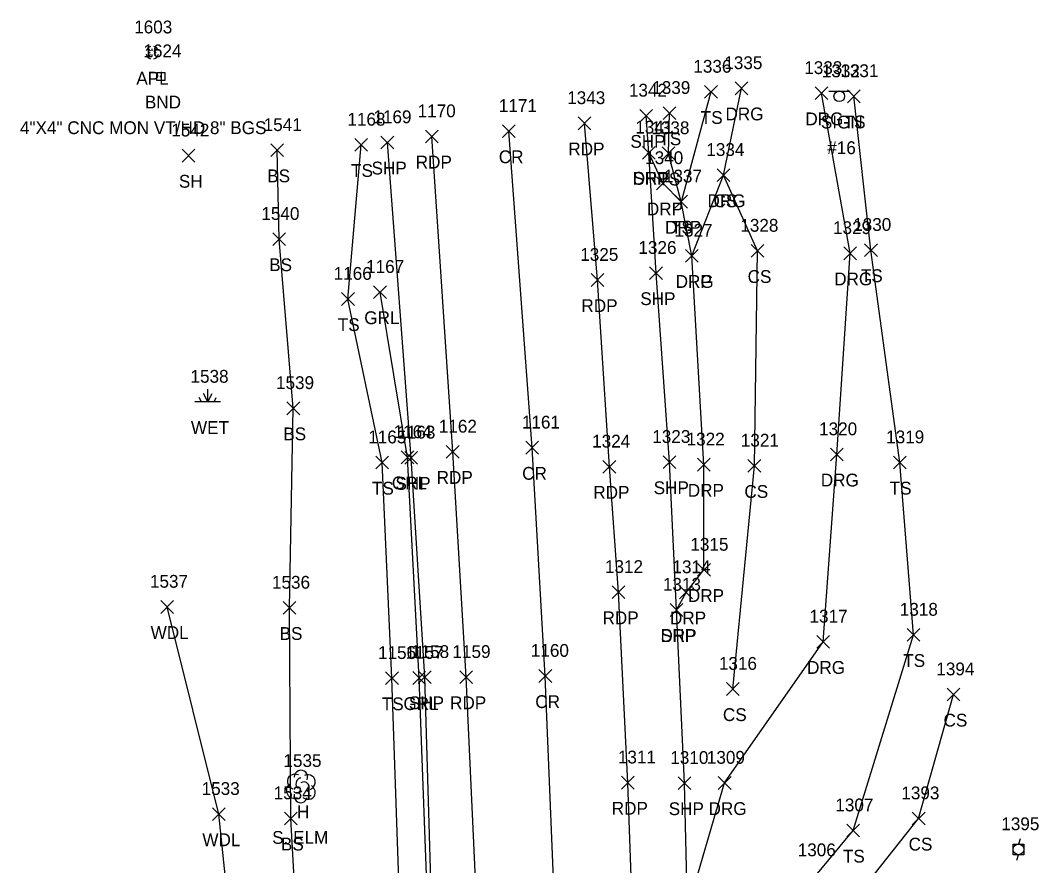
# Model space of a CAD drawing. Extents: x 1618262 to 1622220, y 273782 to 283685.
# Drawn here: x 1621978.9 to 1622138, y 282818.4 to 282950.4 of the extents above; entities that cross this region are included whole.
import ezdxf

# ---------------------------------------------------------------- set-up
doc = ezdxf.new("R2010")
doc.units = 0
for name, color, linetype in [('L_A', 7, 'Continuous'), ('L_C', 7, 'Continuous'), ('L_I', 7, 'Continuous'), ('L_TIC', 7, 'Continuous'), ('LAWA', 7, 'Continuous'), ('LELB', 7, 'Continuous'), ('LTD', 7, 'Continuous'), ('LWET', 7, 'Continuous'), ('M_A', 7, 'Continuous'), ('M_C', 7, 'Continuous'), ('M_I', 7, 'Continuous'), ('MHBP', 7, 'Continuous'), ('MMP', 7, 'Continuous'), ('P_A', 7, 'Continuous'), ('P_I', 7, 'Continuous'), ('P_TIC', 7, 'Continuous'), ('PET', 7, 'Continuous'), ('PRC', 7, 'Continuous'), ('PSP', 7, 'Continuous'), ('R_A', 7, 'Continuous'), ('R_I', 7, 'Continuous'), ('R_TIC', 7, 'Continuous'), ('RDG', 7, 'Continuous'), ('RDP', 7, 'Continuous'), ('RGR', 7, 'Continuous'), ('S_A', 7, 'Continuous'), ('S_C', 7, 'Continuous'), ('S_I', 7, 'Continuous'), ('SSGN', 7, 'Continuous'), ('U_I', 7, 'Continuous'), ('UP', 7, 'Continuous')]:
    doc.layers.add(name, color=color, linetype=linetype)

msp = doc.modelspace()

# ---------------------------------------------------------------- linework, layer by layer
at = {"layer": 'L_TIC'}
for points in [[(1622085.84, 282938.24), (1622087.84, 282940.24)], [(1622087.84, 282938.24), (1622085.84, 282940.24)], [(1622108.18, 282937.55), (1622110.18, 282939.55)], [(1622110.18, 282937.55), (1622108.18, 282939.55)], [(1622079.37, 282934.92), (1622081.37, 282936.92)], [(1622081.37, 282934.92), (1622079.37, 282936.92)], [(1622031.2, 282929.97), (1622033.2, 282931.97)], [(1622033.2, 282929.97), (1622031.2, 282931.97)], [(1622004.21, 282928.28), (1622006.21, 282930.28)], [(1622006.21, 282928.28), (1622004.21, 282930.28)], [(1622018.07, 282929.13), (1622020.07, 282931.13)], [(1622020.07, 282929.13), (1622018.07, 282931.13)], [(1622079.22, 282928.64), (1622081.22, 282930.64)], [(1622081.22, 282928.64), (1622079.22, 282930.64)], [(1622087.81, 282925.24), (1622089.81, 282927.24)], [(1622089.81, 282925.24), (1622087.81, 282927.24)], [(1622081.18, 282921.1), (1622083.18, 282923.1)], [(1622083.18, 282921.1), (1622081.18, 282923.1)], [(1622018.37, 282915.25), (1622020.37, 282917.25)], [(1622020.37, 282915.25), (1622018.37, 282917.25)], [(1622093.12, 282913.41), (1622095.12, 282915.41)], [(1622095.12, 282913.41), (1622093.12, 282915.41)], [(1622110.85, 282913.54), (1622112.85, 282915.54)], [(1622112.85, 282913.54), (1622110.85, 282915.54)], [(1622029.12, 282905.9), (1622031.12, 282907.9)], [(1622031.12, 282905.9), (1622029.12, 282907.9)], [(1622020.58, 282888.84), (1622022.58, 282890.84)], [(1622022.58, 282888.84), (1622020.58, 282890.84)], [(1622034.47, 282880.36), (1622036.47, 282882.36)], [(1622036.47, 282880.36), (1622034.47, 282882.36)], [(1622115.35, 282880.37), (1622117.35, 282882.37)], [(1622117.35, 282880.37), (1622115.35, 282882.37)], [(1622092.63, 282879.85), (1622094.63, 282881.85)], [(1622094.63, 282879.85), (1622092.63, 282881.85)], [(1622000.87, 282857.82), (1622002.87, 282859.82)], [(1622002.87, 282857.82), (1622000.87, 282859.82)], [(1622020, 282857.67), (1622022, 282859.67)], [(1622022, 282857.67), (1622020, 282859.67)], [(1622117.48, 282853.45), (1622119.48, 282855.45)], [(1622119.48, 282853.45), (1622117.48, 282855.45)], [(1622036, 282846.69), (1622038, 282848.69)], [(1622038, 282846.69), (1622036, 282848.69)], [(1622089.27, 282845), (1622091.27, 282847)], [(1622091.27, 282845), (1622089.27, 282847)], [(1622123.75, 282844.14), (1622125.75, 282846.14)], [(1622125.75, 282844.14), (1622123.75, 282846.14)], [(1622008.95, 282825.46), (1622010.95, 282827.46)], [(1622010.95, 282825.46), (1622008.95, 282827.46)], [(1622020.21, 282824.79), (1622022.21, 282826.79)], [(1622022.21, 282824.79), (1622020.21, 282826.79)], [(1622118.29, 282824.78), (1622120.29, 282826.78)], [(1622120.29, 282824.78), (1622118.29, 282826.78)], [(1622108.05, 282822.9), (1622110.05, 282824.9)], [(1622110.05, 282822.9), (1622108.05, 282824.9)]]:
    msp.add_lwpolyline(points, dxfattribs=at)
at = {"layer": 'LAWA'}
msp.add_lwpolyline([(1622012.26, 282719.26), (1622015.51, 282741.12), (1622016.4, 282766.92), (1622013, 282796.99), (1622009.95, 282826.46), (1622001.87, 282858.82)], dxfattribs=at)
at = {"layer": 'LELB'}
for points in [[(1622086.84, 282939.24), (1622082.18, 282922.1), (1622080.22, 282929.64), (1622080.37, 282935.92)], [(1622121.16, 282596.52), (1622112.16, 282596.84), (1622102.98, 282598.76), (1622094.2, 282601.85), (1622088.69, 282605.57), (1622085.73, 282618.96), (1622084.9, 282649.7), (1622087.6, 282681.1), (1622086.98, 282710.97), (1622088.16, 282744.85), (1622088.43, 282782.06), (1622089.47, 282801.31), (1622094.58, 282809.14), (1622103.23, 282816.89), (1622109.05, 282823.9), (1622118.48, 282854.45), (1622116.35, 282881.37), (1622111.85, 282914.54), (1622109.18, 282938.55)], [(1622011.79, 282703.52), (1622017.8, 282718.9), (1622019.25, 282742.06), (1622019.35, 282767.74), (1622022.85, 282795.88), (1622021.21, 282825.79), (1622021, 282858.67), (1622021.58, 282889.84), (1622019.37, 282916.25), (1622019.07, 282930.13)], [(1622031.53, 282480.21), (1622034.92, 282519.52), (1622036.31, 282559.67), (1622038.55, 282600.48), (1622040.58, 282634.79), (1622041.38, 282671.63), (1622041.06, 282708.26), (1622040.54, 282746.86), (1622039.33, 282766.47), (1622038.37, 282807.15), (1622037, 282847.69), (1622035.47, 282881.36), (1622030.12, 282906.9), (1622032.2, 282930.97)], [(1622090.27, 282846), (1622093.63, 282880.85), (1622094.12, 282914.41), (1622088.81, 282926.24)], [(1622091.19, 282690.57), (1622090.7, 282707.3), (1622092.69, 282721.62), (1622095.2, 282734.09), (1622093.37, 282753.63), (1622092.46, 282776.61), (1622095.59, 282800.79), (1622106.62, 282809.83), (1622119.29, 282825.78), (1622124.75, 282845.14)]]:
    msp.add_lwpolyline(points, dxfattribs=at)
at = {"layer": 'LTD'}
msp.add_line((1622022.74, 282830.83), (1622022.74, 282830.83), dxfattribs=at)
msp.add_line((1622022.74, 282830.83), (1622022.74, 282830.83), dxfattribs=at)
msp.add_arc((1622022.78, 282832.27), 1.05, 335.5272, 180.9563, dxfattribs=at)
for centre, major_axis, ratio, start_param, end_param in [((1622021.94, 282831.5), (1.21, -0.51), 0.895232, 1.570796, 4.712389), ((1622022.53, 282831.29), (-0.208, -0.792), 0.645439, 3.141593, 6.283185), ((1622023.24, 282830.67), (-0.5, 0.667), 0.989748, 3.141593, 6.283185), ((1622023.78, 282831.42), (-1.14, -0.48), 0.949671, 1.570796, 4.712389), ((1622021.65, 282830.12), (0.58, -1.04), 0.959034, 3.141593, 6.283185), ((1622022.28, 282830.08), (-0.625, -0.083), 0.423636, 0, 3.141593), ((1622023.74, 282830), (-1.09, 0.79), 0.841452, 1.570796, 4.712389), ((1622022.74, 282829.33), (0.26, 1.06), 0.942809, 1.570796, 4.712389)]:
    msp.add_ellipse(centre, major_axis=major_axis, ratio=ratio, start_param=start_param, end_param=end_param, dxfattribs=at)
at = {"layer": 'LWET'}
for p, q in [((1622008.22, 282890.83), (1622007.55, 282892.16)), ((1622008.22, 282890.83), (1622008.22, 282892.83)), ((1622008.22, 282890.83), (1622008.88, 282892.16)), ((1622010.22, 282890.83), (1622006.22, 282890.83)), ((1622007.22, 282890.83), (1622006.88, 282891.5)), ((1622009.22, 282890.83), (1622009.55, 282891.5))]:
    msp.add_line(p, q, dxfattribs=at)
at = {"layer": 'MHBP'}
msp.add_lwpolyline([(1622000.28, 282942.27), (1622001.53, 282942.27), (1622001.53, 282941.02), (1622000.28, 282941.02)], close=True, dxfattribs=at)
msp.add_circle((1622000.9, 282941.65), 0.0833, dxfattribs=at)
at = {"layer": 'MMP'}
for p, q in [((1621998.9, 282946.02), (1621999.26, 282945.66)), ((1621999.54, 282945.68), (1621999.54, 282945.98)), ((1621999.82, 282945.66), (1622000.18, 282946.02)), ((1621998.9, 282944.74), (1621999.26, 282945.1)), ((1621998.94, 282945.38), (1621999.24, 282945.38)), ((1621999.54, 282944.78), (1621999.54, 282945.08)), ((1621999.82, 282945.1), (1622000.18, 282944.74)), ((1621999.84, 282945.38), (1622000.14, 282945.38))]:
    msp.add_line(p, q, dxfattribs=at)
for start, end in [(105, 165), (15, 75), (195, 255), (285, 345)]:
    msp.add_arc((1621999.54, 282945.38), 1, start, end, dxfattribs=at)
at = {"layer": 'P_TIC'}
for points in [[(1622075.71, 282934.51), (1622077.71, 282936.51)], [(1622077.71, 282934.51), (1622075.71, 282936.51)], [(1622066.07, 282933.34), (1622068.07, 282935.34)], [(1622068.07, 282933.34), (1622066.07, 282935.34)], [(1622042.22, 282931.28), (1622044.22, 282933.28)], [(1622044.22, 282931.28), (1622042.22, 282933.28)], [(1622054.26, 282932.11), (1622056.26, 282934.11)], [(1622056.26, 282932.11), (1622054.26, 282934.11)], [(1622035.28, 282930.35), (1622037.28, 282932.35)], [(1622037.28, 282930.35), (1622035.28, 282932.35)], [(1622076.13, 282928.74), (1622078.13, 282930.74)], [(1622078.13, 282928.74), (1622076.13, 282930.74)], [(1622068.11, 282908.86), (1622070.11, 282910.86)], [(1622070.11, 282908.86), (1622068.11, 282910.86)], [(1622077.26, 282909.95), (1622079.26, 282911.95)], [(1622079.26, 282909.95), (1622077.26, 282911.95)], [(1622045.49, 282882.04), (1622047.49, 282884.04)], [(1622047.49, 282882.04), (1622045.49, 282884.04)], [(1622057.91, 282882.68), (1622059.91, 282884.68)], [(1622059.91, 282882.68), (1622057.91, 282884.68)], [(1622039.01, 282881.11), (1622041.01, 282883.11)], [(1622041.01, 282881.11), (1622039.01, 282883.11)], [(1622079.36, 282880.43), (1622081.36, 282882.43)], [(1622081.36, 282880.43), (1622079.36, 282882.43)], [(1622069.97, 282879.71), (1622071.97, 282881.71)], [(1622071.97, 282879.71), (1622069.97, 282881.71)], [(1622071.41, 282860.12), (1622073.41, 282862.12)], [(1622073.41, 282860.12), (1622071.41, 282862.12)], [(1622080.46, 282857.35), (1622082.46, 282859.35)], [(1622082.46, 282857.35), (1622080.46, 282859.35)], [(1622041.11, 282846.85), (1622043.11, 282848.85)], [(1622043.11, 282846.85), (1622041.11, 282848.85)], [(1622047.59, 282846.85), (1622049.59, 282848.85)], [(1622049.59, 282846.85), (1622047.59, 282848.85)], [(1622059.96, 282847.03), (1622061.96, 282849.03)], [(1622061.96, 282847.03), (1622059.96, 282849.03)], [(1622072.85, 282830.38), (1622074.85, 282832.38)], [(1622074.85, 282830.38), (1622072.85, 282832.38)], [(1622081.7, 282830.31), (1622083.7, 282832.31)], [(1622083.7, 282830.31), (1622081.7, 282832.31)]]:
    msp.add_lwpolyline(points, dxfattribs=at)
at = {"layer": 'PET'}
for points in [[(1622055.39, 282357.79), (1622060.73, 282405.55), (1622064, 282439.1), (1622067.39, 282476.75), (1622069.45, 282501.97), (1622071.17, 282531.22), (1622072.59, 282558.99), (1622074.38, 282609.31), (1622075.4, 282650.49), (1622076.38, 282682.88), (1622076.73, 282709.49), (1622076.47, 282742.79), (1622075.65, 282781.75), (1622073.85, 282831.38), (1622072.41, 282861.12), (1622070.97, 282880.71), (1622069.11, 282909.86), (1622067.07, 282934.34)], [(1622031.4, 282363.08), (1622036.53, 282409.61), (1622039.66, 282443.45), (1622042.91, 282478.81), (1622045.92, 282518.25), (1622048.16, 282558.34), (1622049.91, 282599.51), (1622051.11, 282634.14), (1622051.9, 282670.59), (1622052.33, 282709.81), (1622052.15, 282746.85), (1622051.43, 282768.15), (1622050.47, 282807.31), (1622048.59, 282847.85), (1622046.49, 282883.04), (1622043.22, 282932.28)]]:
    msp.add_lwpolyline(points, dxfattribs=at)
at = {"layer": 'PRC'}
msp.add_lwpolyline([(1622043.29, 282360.39), (1622048.9, 282407.64), (1622051.69, 282440.97), (1622055.31, 282477.63), (1622057.87, 282516.74), (1622059.99, 282557.51), (1622061.58, 282597.2), (1622062.84, 282633.2), (1622063.88, 282668.54), (1622064.41, 282708.38), (1622064.5, 282747.03), (1622063.87, 282768.18), (1622062.59, 282807.54), (1622060.96, 282848.03), (1622058.91, 282883.68), (1622055.26, 282933.11)], dxfattribs=at)
at = {"layer": 'PSP'}
for points in [[(1622063.9, 282356.42), (1622068.96, 282404.45), (1622072.02, 282437.73), (1622074.67, 282475.61), (1622076.63, 282501.43), (1622078.27, 282531.06), (1622079.38, 282546.3), (1622079.58, 282558.79), (1622081.73, 282610.73), (1622082.59, 282649.97), (1622083.39, 282682.72), (1622083.74, 282709.96), (1622083.62, 282744.12), (1622083.45, 282781.35), (1622083.17, 282811.55), (1622082.7, 282831.31), (1622081.46, 282858.35), (1622080.36, 282881.43), (1622078.26, 282910.95), (1622077.13, 282929.74), (1622076.71, 282935.51)], [(1622024.53, 282364.7), (1622029.22, 282410.34), (1622032.13, 282444.4), (1622034.72, 282480.17), (1622038.06, 282518.94), (1622040.19, 282559.98), (1622041.78, 282599.8), (1622043.58, 282635.08), (1622043.93, 282671.71), (1622044.18, 282709.62), (1622044.43, 282746.88), (1622044.14, 282766.85), (1622043.31, 282807.36), (1622042.11, 282847.85), (1622040.01, 282882.11), (1622036.28, 282931.35)]]:
    msp.add_lwpolyline(points, dxfattribs=at)
at = {"layer": 'R_TIC'}
for points in [[(1622090.62, 282938.8), (1622092.62, 282940.8)], [(1622092.62, 282938.8), (1622090.62, 282940.8)], [(1622103.11, 282938.03), (1622105.11, 282940.03)], [(1622105.11, 282938.03), (1622103.11, 282940.03)], [(1622076.13, 282928.74), (1622078.13, 282930.74)], [(1622078.13, 282928.74), (1622076.13, 282930.74)], [(1622087.81, 282925.24), (1622089.81, 282927.24)], [(1622089.81, 282925.24), (1622087.81, 282927.24)], [(1622078.34, 282923.97), (1622080.34, 282925.97)], [(1622080.34, 282923.97), (1622078.34, 282925.97)], [(1622081.18, 282921.1), (1622083.18, 282923.1)], [(1622083.18, 282921.1), (1622081.18, 282923.1)], [(1622082.84, 282912.64), (1622084.84, 282914.64)], [(1622084.84, 282912.64), (1622082.84, 282914.64)], [(1622082.84, 282912.64), (1622084.84, 282914.64)], [(1622084.84, 282912.64), (1622082.84, 282914.64)], [(1622107.61, 282913.04), (1622109.61, 282915.04)], [(1622109.61, 282913.04), (1622107.61, 282915.04)], [(1622034.13, 282906.98), (1622036.13, 282908.98)], [(1622036.13, 282906.98), (1622034.13, 282908.98)], [(1622038.44, 282881.18), (1622040.44, 282883.18)], [(1622040.44, 282881.18), (1622038.44, 282883.18)], [(1622105.52, 282881.63), (1622107.52, 282883.63)], [(1622107.52, 282881.63), (1622105.52, 282883.63)], [(1622084.73, 282880.03), (1622086.73, 282882.03)], [(1622086.73, 282880.03), (1622084.73, 282882.03)], [(1622084.75, 282863.6), (1622086.75, 282865.6)], [(1622086.75, 282863.6), (1622084.75, 282865.6)], [(1622081.95, 282860.09), (1622083.95, 282862.09)], [(1622083.95, 282860.09), (1622081.95, 282862.09)], [(1622080.46, 282857.35), (1622082.46, 282859.35)], [(1622082.46, 282857.35), (1622080.46, 282859.35)], [(1622103.37, 282852.37), (1622105.37, 282854.37)], [(1622105.37, 282852.37), (1622103.37, 282854.37)], [(1622040.25, 282846.72), (1622042.25, 282848.72)], [(1622042.25, 282846.72), (1622040.25, 282848.72)], [(1622087.98, 282830.33), (1622089.98, 282832.33)], [(1622089.98, 282830.33), (1622087.98, 282832.33)]]:
    msp.add_lwpolyline(points, dxfattribs=at)
at = {"layer": 'RDG'}
for points in [[(1622083.84, 282913.64), (1622088.81, 282926.24), (1622091.62, 282939.8)], [(1622083.17, 282811.55), (1622088.98, 282831.33), (1622104.37, 282853.37), (1622106.52, 282882.63), (1622108.61, 282914.04), (1622104.11, 282939.03)]]:
    msp.add_lwpolyline(points, dxfattribs=at)
at = {"layer": 'RDP'}
msp.add_lwpolyline([(1622081.46, 282858.35), (1622082.95, 282861.09), (1622085.75, 282864.6), (1622085.73, 282881.03), (1622083.84, 282913.64), (1622082.18, 282922.1), (1622079.34, 282924.97), (1622077.13, 282929.74)], dxfattribs=at)
at = {"layer": 'RGR'}
msp.add_lwpolyline([(1622023.48, 282364.89), (1622028.19, 282410.18), (1622031.23, 282444.19), (1622033.74, 282480.24), (1622036.8, 282518.9), (1622039.04, 282560.07), (1622040.98, 282599.77), (1622042.92, 282635.17), (1622043.06, 282671.76), (1622043.62, 282709.36), (1622043.68, 282746.97), (1622043.35, 282766.73), (1622042.76, 282807.19), (1622041.25, 282847.72), (1622039.44, 282882.18), (1622035.13, 282907.98)], dxfattribs=at)
at = {"layer": 'SSGN'}
for p, q in [((1622105.24, 282939.38), (1622108.57, 282939.38)), ((1622106.89, 282938.55), (1622106.89, 282938.55))]:
    msp.add_line(p, q, dxfattribs=at)
msp.add_circle((1622106.89, 282938.55), 0.833, dxfattribs=at)
at = {"layer": 'UP'}
for p, q in [((1622134.07, 282820.12), (1622134.07, 282821.79)), ((1622134.07, 282821.79), (1622135.73, 282821.79)), ((1622135.15, 282822.62), (1622134.9, 282821.79)), ((1622135.73, 282821.79), (1622135.73, 282820.12)), ((1622135.73, 282820.12), (1622134.07, 282820.12)), ((1622134.65, 282819.29), (1622134.9, 282820.12)), ((1622134.9, 282820.96), (1622134.9, 282820.96))]:
    msp.add_line(p, q, dxfattribs=at)
msp.add_circle((1622134.9, 282820.96), 0.833, dxfattribs=at)

# ---------------------------------------------------------------- texts
at = {"layer": 'L_A'}
for s, p in [('TS', (1622085.25, 282934.24)), ('TS', (1622107.59, 282933.55)), ('TS', (1622078.78, 282930.92)), ('BS', (1622017.51, 282925.13)), ('TS', (1622030.61, 282925.97)), ('SH', (1622003.7, 282924.28)), ('TS', (1622078.63, 282924.64)), ('CS', (1622087.25, 282921.24)), ('TS', (1622080.59, 282917.1)), ('BS', (1622017.81, 282911.25)), ('CS', (1622092.57, 282909.41)), ('TS', (1622110.26, 282909.54)), ('TS', (1622028.53, 282901.9)), ('WET', (1622005.59, 282885.83)), ('BS', (1622020.02, 282884.84)), ('TS', (1622033.87, 282876.36)), ('CS', (1622092.07, 282875.85)), ('TS', (1622114.76, 282876.37)), ('WDL', (1621999.29, 282853.82)), ('BS', (1622019.44, 282853.67)), ('TS', (1622116.89, 282849.45)), ('TS', (1622035.41, 282842.69)), ('CS', (1622088.71, 282841)), ('CS', (1622123.19, 282840.14)), ('H', (1622022.17, 282825.83)), ('WDL', (1622007.37, 282821.46)), ('BS', (1622019.65, 282820.79)), ('CS', (1622117.73, 282820.78)), ('TS', (1622107.46, 282818.9))]:
    msp.add_text(s, height=2, dxfattribs=at).set_placement(p)
at = {"layer": 'L_C'}
msp.add_text('S. ELM', height=2, dxfattribs=at).set_placement((1622018.28, 282821.83))
at = {"layer": 'L_I'}
for s, p in [('1336', (1622084.09, 282942.24)), ('1331', (1622107.06, 282941.55)), ('1339', (1622077.67, 282938.92)), ('1541', (1622016.95, 282933.13)), ('1168', (1622030.03, 282933.97)), ('1542', (1622002.52, 282932.28)), ('1338', (1622077.53, 282932.64)), ('1334', (1622086.12, 282929.24)), ('1337', (1622079.49, 282925.1)), ('1540', (1622016.59, 282919.25)), ('1328', (1622091.43, 282917.41)), ('1330', (1622109.07, 282917.54)), ('1166', (1622027.89, 282909.9)), ('1538', (1622005.52, 282893.83)), ('1539', (1622018.88, 282892.84)), ('1165', (1622033.29, 282884.36)), ('1321', (1622091.51, 282883.85)), ('1319', (1622114.22, 282884.37)), ('1537', (1621999.18, 282861.82)), ('1536', (1622018.25, 282861.67)), ('1318', (1622116.35, 282857.45)), ('1156', (1622034.82, 282850.69)), ('1316', (1622088.08, 282849)), ('1394', (1622122.06, 282848.14)), ('1535', (1622020.04, 282833.83)), ('1533', (1622007.26, 282829.46)), ('1534', (1622018.51, 282828.79)), ('1393', (1622116.59, 282828.78)), ('1307', (1622106.28, 282826.9)), ('1306', (1622100.4, 282819.89))]:
    msp.add_text(s, height=2, dxfattribs=at).set_placement(p)
at = {"layer": 'M_A'}
for s, p in [('APL', (1621997.05, 282940.38)), ('BND', (1621998.39, 282936.65))]:
    msp.add_text(s, height=2, dxfattribs=at).set_placement(p)
at = {"layer": 'M_C'}
msp.add_text('4"X4" CNC MON VT/HD 8" BGS', height=2, dxfattribs=at).set_placement((1621978.87, 282932.65))
at = {"layer": 'M_I'}
for s, p in [('1603', (1621996.72, 282948.38)), ('1624', (1621998.16, 282944.65))]:
    msp.add_text(s, height=2, dxfattribs=at).set_placement(p)
at = {"layer": 'P_A'}
for s, p in [('SHP', (1622074.25, 282930.51)), ('CR', (1622053.69, 282928.11)), ('RDP', (1622064.56, 282929.34)), ('SHP', (1622033.81, 282926.35)), ('RDP', (1622040.71, 282927.28)), ('SHP', (1622074.67, 282924.74)), ('SHP', (1622075.8, 282905.95)), ('RDP', (1622066.6, 282904.86)), ('CR', (1622057.34, 282878.68)), ('SHP', (1622037.54, 282877.11)), ('RDP', (1622043.98, 282878.04)), ('RDP', (1622068.46, 282875.71)), ('SHP', (1622077.89, 282876.43)), ('RDP', (1622069.9, 282856.12)), ('SHP', (1622079, 282853.35)), ('SHP', (1622039.64, 282842.85)), ('RDP', (1622046.08, 282842.85)), ('CR', (1622059.39, 282843.03)), ('RDP', (1622071.34, 282826.38)), ('SHP', (1622080.24, 282826.31))]:
    msp.add_text(s, height=2, dxfattribs=at).set_placement(p)
at = {"layer": 'P_I'}
for s, p in [('1342', (1622074.02, 282938.51)), ('1171', (1622053.7, 282936.11)), ('1343', (1622064.38, 282937.34)), ('1169', (1622034.1, 282934.35)), ('1170', (1622041.01, 282935.28)), ('1341', (1622075.01, 282932.74)), ('1326', (1622075.51, 282913.95)), ('1325', (1622066.42, 282912.86)), ('1161', (1622057.3, 282886.68)), ('1163', (1622037.83, 282885.11)), ('1162', (1622044.32, 282886.04)), ('1324', (1622068.28, 282883.71)), ('1323', (1622077.67, 282884.43)), ('1312', (1622070.28, 282864.12)), ('1313', (1622079.33, 282861.35)), ('1158', (1622039.98, 282850.85)), ('1159', (1622046.45, 282850.85)), ('1160', (1622058.7, 282851.03)), ('1311', (1622072.3, 282834.38)), ('1310', (1622080.49, 282834.31))]:
    msp.add_text(s, height=2, dxfattribs=at).set_placement(p)
at = {"layer": 'R_A'}
for s, p in [('DRG', (1622089.11, 282934.8)), ('DRG', (1622101.6, 282934.03)), ('DRP', (1622074.62, 282924.74)), ('DRP', (1622076.83, 282919.97)), ('DRG', (1622086.3, 282921.24)), ('DRP', (1622079.67, 282917.1)), ('DRG', (1622106.1, 282909.04)), ('DRG', (1622081.33, 282908.64)), ('DRP', (1622081.33, 282908.64)), ('GRL', (1622032.67, 282902.98)), ('GRL', (1622036.98, 282877.18)), ('DRG', (1622104.01, 282877.63)), ('DRP', (1622083.22, 282876.03)), ('DRP', (1622083.24, 282859.6)), ('DRP', (1622080.44, 282856.09)), ('DRP', (1622078.95, 282853.35)), ('DRG', (1622101.86, 282848.37)), ('GRL', (1622038.79, 282842.72)), ('DRG', (1622086.47, 282826.33))]:
    msp.add_text(s, height=2, dxfattribs=at).set_placement(p)
at = {"layer": 'R_I'}
for s, p in [('1335', (1622088.93, 282942.8)), ('1333', (1622101.42, 282942.03)), ('1341', (1622075.01, 282932.74)), ('1340', (1622076.56, 282927.97)), ('1334', (1622086.12, 282929.24)), ('1337', (1622079.49, 282925.1)), ('1329', (1622105.91, 282917.04)), ('1327', (1622081.15, 282916.64)), ('1327', (1622081.15, 282916.64)), ('1167', (1622032.96, 282910.98)), ('1164', (1622037.26, 282885.18)), ('1320', (1622103.74, 282885.63)), ('1322', (1622083.04, 282884.03)), ('1315', (1622083.63, 282867.6)), ('1314', (1622080.83, 282864.09)), ('1313', (1622079.33, 282861.35)), ('1317', (1622102.24, 282856.37)), ('1157', (1622039.13, 282850.72)), ('1309', (1622086.2, 282834.33))]:
    msp.add_text(s, height=2, dxfattribs=at).set_placement(p)
at = {"layer": 'S_A'}
msp.add_text('SIGN', height=2, dxfattribs=at).set_placement((1622104.02, 282933.53))
at = {"layer": 'S_C'}
msp.add_text('#16', height=2, dxfattribs=at).set_placement((1622105.02, 282929.53))
at = {"layer": 'S_I'}
msp.add_text('1332', height=2, dxfattribs=at).set_placement((1622104.17, 282941.53))
at = {"layer": 'U_I'}
msp.add_text('1395', height=2, dxfattribs=at).set_placement((1622132.21, 282823.96))

doc.saveas('drawing.dxf')
